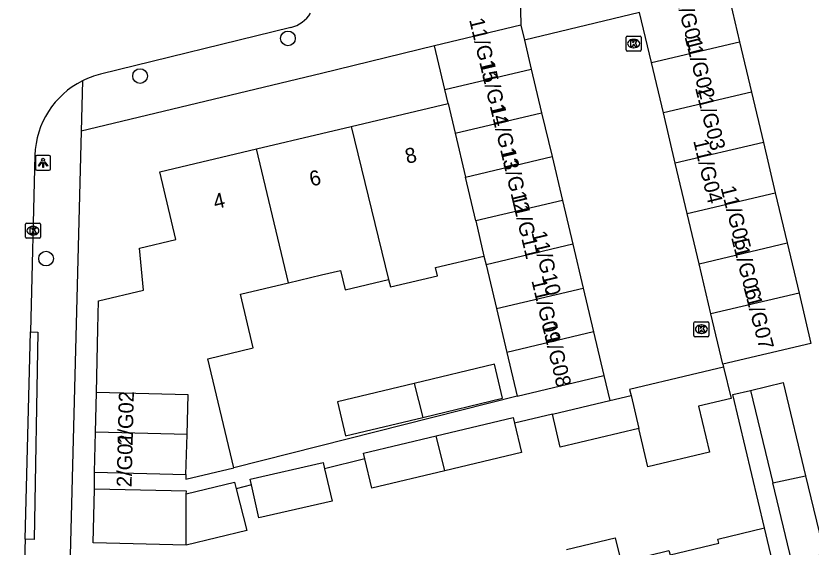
# Model space of a CAD drawing. Extents: x 162082 to 163393, y 388091 to 388632.
# Drawn here: x 162979.6 to 163032.6, y 388126.3 to 388161.7 of the extents above; entities that cross this region are included whole.
import ezdxf

# ---------------------------------------------------------------- set-up
doc = ezdxf.new("R2010")
doc.units = 0
for name, color, linetype in [('IMGEO_Boom', 7, 'Continuous'), ('IMGEO_Kolk', 7, 'Continuous'), ('IMGEO_Lichtpunt', 7, 'Continuous'), ('IMGEO_Muur', 7, 'Continuous'), ('IMGEO_Pand', 7, 'Continuous'), ('IMGEO_Pand_nummerreeks', 7, 'Continuous'), ('IMGEO_Rijbaan_lokaal_open', 7, 'Continuous'), ('IMGEO_Voetpad_open', 7, 'Continuous')]:
    doc.layers.add(name, color=color, linetype=linetype)

msp = doc.modelspace()

# ---------------------------------------------------------------- linework, layer by layer
at = {"layer": 'IMGEO_Boom'}
for centre in [(162997.773, 388160.238), (162987.922, 388157.727), (162981.659, 388145.557)]:
    msp.add_circle(centre, 0.489, dxfattribs=at)
at = {"layer": 'IMGEO_Kolk'}
for p, q in [((163020.299, 388159.464), (163020.299, 388160.316)), ((163020.374, 388160.39), (163021.226, 388160.39)), ((163020.787, 388160.17), (163020.812, 388160.17)), ((163021.3, 388160.316), (163021.3, 388159.464)), ((163020.81, 388159.61), (163020.785, 388159.61)), ((163021.226, 388159.39), (163020.374, 388159.39)), ((162980.285, 388146.994), (162980.285, 388147.846)), ((162980.36, 388147.92), (162981.212, 388147.92)), ((162981.286, 388147.846), (162981.286, 388146.994)), ((162980.773, 388147.7), (162980.798, 388147.7)), ((162981.212, 388146.92), (162980.36, 388146.92)), ((162980.796, 388147.14), (162980.771, 388147.14)), ((163024.813, 388140.43), (163024.813, 388141.282)), ((163024.888, 388141.356), (163025.74, 388141.356)), ((163025.301, 388141.136), (163025.326, 388141.136)), ((163025.814, 388141.282), (163025.814, 388140.43)), ((163025.74, 388140.356), (163024.888, 388140.356)), ((163025.324, 388140.576), (163025.299, 388140.576))]:
    msp.add_line(p, q, dxfattribs=at)
for points in [[(163020.299, 388159.464), (163020.299, 388160.316)], [(163020.374, 388160.39), (163021.226, 388160.39)], [(163020.62, 388160.09), (163020.743, 388160.09), (163020.743, 388159.939), (163020.873, 388160.09), (163021.037, 388160.09), (163020.891, 388159.939), (163021.044, 388159.69), (163020.892, 388159.69), (163020.807, 388159.854), (163020.743, 388159.787), (163020.743, 388159.69), (163020.62, 388159.69), (163020.62, 388160.09)], [(163021.3, 388160.316), (163021.3, 388159.464)], [(163021.226, 388159.39), (163020.374, 388159.39)], [(162980.285, 388146.994), (162980.285, 388147.846)], [(162980.36, 388147.92), (162981.212, 388147.92)], [(162981.286, 388147.846), (162981.286, 388146.994)], [(162980.606, 388147.62), (162980.729, 388147.62), (162980.729, 388147.469), (162980.859, 388147.62), (162981.023, 388147.62), (162980.877, 388147.469), (162981.03, 388147.22), (162980.878, 388147.22), (162980.793, 388147.384), (162980.729, 388147.317), (162980.729, 388147.22), (162980.606, 388147.22), (162980.606, 388147.62)], [(162981.212, 388146.92), (162980.36, 388146.92)], [(163024.813, 388140.43), (163024.813, 388141.282)], [(163024.888, 388141.356), (163025.74, 388141.356)], [(163025.134, 388141.056), (163025.257, 388141.056), (163025.257, 388140.905), (163025.387, 388141.056), (163025.551, 388141.056), (163025.405, 388140.905), (163025.558, 388140.656), (163025.406, 388140.656), (163025.321, 388140.82), (163025.257, 388140.753), (163025.257, 388140.656), (163025.134, 388140.656), (163025.134, 388141.056)], [(163025.814, 388141.282), (163025.814, 388140.43)], [(163025.74, 388140.356), (163024.888, 388140.356)]]:
    msp.add_lwpolyline(points, dxfattribs=at)
for centre, start, end in [((163020.376, 388160.314), 91.552, 178.448), ((163020.376, 388160.314), 91.552, 178.448), ((163021.224, 388160.314), 1.552, 88.448), ((163021.224, 388160.314), 1.552, 88.448), ((163020.376, 388159.466), 181.552, 268.448), ((163020.376, 388159.466), 181.552, 268.448), ((163021.224, 388159.466), 271.552, 358.448), ((163021.224, 388159.466), 271.552, 358.448), ((162980.362, 388147.844), 91.552, 178.448), ((162980.362, 388147.844), 91.552, 178.448), ((162981.21, 388147.844), 1.552, 88.448), ((162981.21, 388147.844), 1.552, 88.448), ((162980.362, 388146.996), 181.552, 268.448), ((162980.362, 388146.996), 181.552, 268.448), ((162981.21, 388146.996), 271.552, 358.448), ((162981.21, 388146.996), 271.552, 358.448), ((163024.89, 388141.28), 91.552, 178.448), ((163024.89, 388141.28), 91.552, 178.448), ((163025.738, 388141.28), 1.552, 88.448), ((163025.738, 388141.28), 1.552, 88.448), ((163024.89, 388140.432), 181.552, 268.448), ((163024.89, 388140.432), 181.552, 268.448), ((163025.738, 388140.432), 271.552, 358.448), ((163025.738, 388140.432), 271.552, 358.448)]:
    msp.add_arc(centre, 0.0765, start, end, dxfattribs=at)
for centre, major_axis, ratio, start_param, end_param in [((163020.786, 388159.89), (-0.387, 0.002), 0.722429, 4.712389, 7.853982), ((163020.811, 388159.89), (-0.39, 0.002), 0.717154, 1.570796, 4.712389), ((162980.772, 388147.42), (-0.387, 0.002), 0.722429, 4.712389, 7.853982), ((162980.797, 388147.42), (-0.39, 0.002), 0.717154, 1.570796, 4.712389), ((163025.3, 388140.856), (-0.387, 0.002), 0.722429, 4.712389, 7.853982), ((163025.325, 388140.856), (-0.39, 0.002), 0.717154, 1.570796, 4.712389)]:
    msp.add_ellipse(centre, major_axis=major_axis, ratio=ratio, start_param=start_param, end_param=end_param, dxfattribs=at)
at = {"layer": 'IMGEO_Lichtpunt'}
for p, q in [((162980.96, 388152.348), (162980.96, 388151.541)), ((162980.96, 388152.348), (162980.96, 388151.541)), ((162981.862, 388152.443), (162981.054, 388152.443)), ((162981.862, 388152.443), (162981.054, 388152.443)), ((162981.956, 388151.541), (162981.956, 388152.348)), ((162981.956, 388151.541), (162981.956, 388152.348)), ((162981.054, 388151.447), (162981.862, 388151.447)), ((162981.054, 388151.447), (162981.862, 388151.447))]:
    msp.add_line(p, q, dxfattribs=at)
for points in [[(162981.334, 388152.012), (162981.373, 388151.984), (162981.185, 388151.722), (162981.147, 388151.749), (162981.334, 388152.012)], [(162981.546, 388151.984), (162981.584, 388152.011), (162981.771, 388151.749), (162981.732, 388151.721), (162981.546, 388151.984)], [(162981.436, 388151.964), (162981.483, 388151.964), (162981.483, 388151.642), (162981.436, 388151.642), (162981.436, 388151.964)]]:
    msp.add_lwpolyline(points, dxfattribs=at)
msp.add_circle((162981.459, 388152.146), 0.0994, dxfattribs=at)
for centre, start, end in [((162981.054, 388152.348), 90, 180), ((162981.054, 388152.348), 90, 180), ((162981.862, 388152.348), 0, 90), ((162981.862, 388152.348), 0, 90), ((162981.054, 388151.541), 180, 270), ((162981.054, 388151.541), 180, 270), ((162981.862, 388151.541), 270, 0), ((162981.862, 388151.541), 270, 360)]:
    msp.add_arc(centre, 0.0946, start, end, dxfattribs=at)
at = {"layer": 'IMGEO_Muur'}
msp.add_lwpolyline([(162983.292, 388126.643), (162983.093, 388118.887)], dxfattribs=at)
at = {"layer": 'IMGEO_Pand'}
for points in [[(163027.064, 388163.356), (163027.856, 388160.006)], [(163021.992, 388158.62), (163021.2, 388161.969)], [(163013.29, 388161.115), (163007.525, 388159.751)], [(163013.29, 388161.115), (163013.524, 388160.125)], [(163013.524, 388160.125), (163013.981, 388158.196)], [(163021.992, 388158.62), (163027.856, 388160.006)], [(163027.856, 388160.006), (163028.648, 388156.656)], [(163008.216, 388156.831), (163007.525, 388159.751)], [(163022.784, 388155.269), (163021.992, 388158.62)], [(163008.216, 388156.831), (163013.981, 388158.196)], [(163013.981, 388158.196), (163014.672, 388155.277)], [(163008.439, 388155.888), (163008.216, 388156.831)], [(163028.648, 388156.656), (163022.784, 388155.269)], [(163028.648, 388156.656), (163029.44, 388153.306)], [(163001.99, 388154.362), (163008.439, 388155.888)], [(163008.439, 388155.888), (163008.904, 388153.911)], [(163008.904, 388153.911), (163014.672, 388155.277)], [(163014.672, 388155.277), (163015.363, 388152.358)], [(163023.576, 388151.919), (163022.784, 388155.269)], [(162995.687, 388152.87), (163000, 388153.891), (163001.99, 388154.362)], [(163001.99, 388154.362), (163004.479, 388144.174)], [(163008.904, 388153.911), (163009.59, 388150.991)], [(163029.44, 388153.306), (163023.576, 388151.919)], [(163029.44, 388153.306), (163030.232, 388149.955)], [(162985.012, 388136.641), (162985.117, 388140.885), (162985.163, 388142.746), (162988.151, 388143.454), (162987.876, 388146.263), (162990.309, 388146.839), (162989.242, 388151.344), (162995.687, 388152.87)], [(162997.798, 388143.951), (162995.687, 388152.87)], [(163009.59, 388150.991), (163015.363, 388152.358)], [(163015.363, 388152.358), (163016.054, 388149.439)], [(163024.368, 388148.569), (163023.576, 388151.919)], [(163010.277, 388148.071), (163009.59, 388150.991)], [(163024.368, 388148.569), (163030.232, 388149.955)], [(163030.232, 388149.955), (163031.024, 388146.605)], [(163016.054, 388149.439), (163010.277, 388148.071)], [(163016.054, 388149.439), (163016.745, 388146.519)], [(163025.16, 388145.219), (163024.368, 388148.569)], [(163010.277, 388148.071), (163010.827, 388145.732)], [(163016.745, 388146.519), (163010.965, 388145.151)], [(163016.745, 388146.519), (163017.436, 388143.6)], [(163025.16, 388145.219), (163031.024, 388146.605)], [(163031.024, 388146.605), (163031.816, 388143.255)], [(163004.479, 388144.174), (163004.596, 388143.68), (163007.733, 388144.423), (163007.604, 388144.969), (163010.827, 388145.732)], [(163010.827, 388145.732), (163010.965, 388145.151)], [(163010.965, 388145.151), (163011.656, 388142.232)], [(163025.952, 388141.869), (163025.16, 388145.219)], [(162997.798, 388143.951), (163000, 388144.472), (163001.277, 388144.774), (163001.581, 388143.489), (163004.479, 388144.174)], [(162994.164, 388131.611), (162992.441, 388138.891), (162995.456, 388139.605), (162994.606, 388143.195), (162997.798, 388143.951)], [(163011.656, 388142.232), (163017.436, 388143.6)], [(163017.436, 388143.6), (163018.127, 388140.681)], [(163031.816, 388143.255), (163025.952, 388141.869)], [(163031.816, 388143.255), (163032.608, 388139.905), (163026.744, 388138.518)], [(163011.656, 388142.232), (163012.347, 388139.313)], [(163026.744, 388138.518), (163025.952, 388141.869)], [(163018.127, 388140.681), (163012.347, 388139.313)], [(163018.127, 388140.681), (163018.818, 388137.762)], [(163012.347, 388139.313), (163013.038, 388136.394)], [(163006.747, 388134.974), (163012.07, 388136.254), (163011.522, 388138.53), (163006.19, 388137.246)], [(163026.79, 388138.328), (163024.622, 388137.815), (163020.53, 388136.847), (163020.627, 388136.435)], [(163026.79, 388138.328), (163027.287, 388136.232), (163025.118, 388135.719), (163025.843, 388132.657), (163021.75, 388131.689), (163021.147, 388134.239)], [(163013.038, 388136.394), (163018.818, 388137.762)], [(163006.19, 388137.246), (163001.069, 388136.014), (163001.616, 388133.739), (163006.747, 388134.974)], [(163006.19, 388137.246), (163006.747, 388134.974)], [(163028.593, 388136.779), (163030.759, 388137.3), (163032.254, 388131.088)], [(162984.946, 388133.989), (162985.012, 388136.641)], [(162991.053, 388133.835), (162991.132, 388136.478), (162985.012, 388136.641)], [(163028.593, 388136.779), (163030.078, 388130.611)], [(163015.392, 388135.197), (163019.223, 388136.103)], [(163019.223, 388136.103), (163020.627, 388136.435)], [(163020.627, 388136.435), (163021.147, 388134.239)], [(163021.147, 388134.239), (163015.911, 388133.001), (163015.392, 388135.197)], [(163007.649, 388133.745), (163012.763, 388134.969), (163012.854, 388134.588)], [(163012.854, 388134.588), (163013.32, 388132.643), (163008.227, 388131.425)], [(162984.88, 388131.337), (162984.946, 388133.989)], [(162991.053, 388133.835), (162984.946, 388133.989)], [(162990.972, 388131.168), (162991.053, 388133.835)], [(163002.888, 388132.215), (163002.8, 388132.584), (163007.649, 388133.745)], [(163008.227, 388131.425), (163007.649, 388133.745)], [(162995.34, 388130.478), (162995.254, 388130.853), (163000.121, 388131.964), (163000.215, 388131.551)], [(163008.227, 388131.425), (163003.357, 388130.259), (163002.888, 388132.215)], [(162984.88, 388131.337), (162990.972, 388131.168)], [(162990.972, 388131.168), (162990.963, 388130.853), (162994.164, 388131.611)], [(163000.215, 388131.551), (163000.709, 388129.388), (162995.842, 388128.278), (162995.34, 388130.478)], [(163030.078, 388130.611), (163032.254, 388131.088)], [(163032.254, 388131.088), (163033.511, 388125.868), (163031.565, 388125.399)], [(162991.001, 388129.89), (162994.209, 388130.666), (162994.322, 388130.219)], [(163031.565, 388125.399), (163031.346, 388125.346), (163030.078, 388130.611)], [(162991.001, 388126.47), (162984.799, 388126.609), (162984.88, 388130.204)], [(162991.001, 388129.89), (162991.005, 388130.066), (162984.88, 388130.204)], [(162994.322, 388130.219), (162995.024, 388127.441), (162991.001, 388126.47)], [(162991.001, 388126.47), (162991.001, 388129.89)], [(163022.972, 388126.058), (163023.153, 388126.101), (163023.223, 388125.809), (163026.465, 388126.588), (163026.399, 388126.861), (163029.513, 388127.607)], [(163031.936, 388117.503), (163030.77, 388122.366), (163029.513, 388127.607)], [(163016.329, 388126.175), (163019.576, 388126.954), (163019.964, 388125.336), (163022.972, 388126.058)]]:
    msp.add_lwpolyline(points, dxfattribs=at)
at = {"layer": 'IMGEO_Rijbaan_lokaal_open'}
for points in [[(163013.196, 388165.179), (163013.29, 388161.115)], [(163021.2, 388161.969), (163013.524, 388160.125)], [(162997.969, 388160.96), (162985.285, 388157.849)], [(162980.912, 388152.448), (162980.612, 388140.675)], [(162980.259, 388126.871), (162980.612, 388140.675)], [(163026.744, 388138.518), (163026.79, 388138.328)], [(163018.818, 388137.762), (163019.223, 388136.103)], [(162980.259, 388126.871), (162980.188, 388124.07), (162980.079, 388114.681), (162979.65, 388101.666)]]:
    msp.add_lwpolyline(points, dxfattribs=at)
for centre, radius, start, end in [((162997.461, 388163.029), 2.13, 283.7891, 328.7261), ((162986.673, 388152.218), 5.8, 103.8504, 116.5508), ((162986.652, 388152.271), 5.742, 116.593, 178.2361)]:
    msp.add_arc(centre, radius, start, end, dxfattribs=at)
at = {"layer": 'IMGEO_Voetpad_open'}
for points in [[(163007.525, 388159.751), (163000, 388157.905), (162983.995, 388154.044)], [(162984.081, 388157.406), (162983.995, 388154.044)], [(162983.995, 388154.044), (162983.292, 388126.643), (162983.093, 388118.887), (162982.649, 388101.605)], [(162980.612, 388140.675), (162981.111, 388140.658), (162980.865, 388126.85), (162980.259, 388126.871)], [(163029.513, 388127.607), (163027.41, 388136.499), (163028.593, 388136.779)], [(163013.038, 388136.394), (162994.164, 388131.611)], [(163015.392, 388135.197), (163012.854, 388134.588)], [(163002.888, 388132.215), (163000.215, 388131.551)], [(162984.88, 388130.204), (162984.88, 388131.337)], [(162995.34, 388130.478), (162994.322, 388130.219)]]:
    msp.add_lwpolyline(points, dxfattribs=at)

# ---------------------------------------------------------------- texts
at = {"layer": 'IMGEO_Pand_nummerreeks'}
for s, rotation, p in [('11/G01', 284.3952, (163023.421, 388163.606)), ('11/G15', 283.4185, (163009.836, 388161.481)), ('11/G02', 284.3952, (163024.182, 388160.346)), ('11/G14', 283.4194, (163010.531, 388158.568)), ('11/G03', 284.3952, (163024.883, 388156.937)), ('11/G13', 283.4194, (163011.226, 388155.656)), ('11/G04', 283.3015, (163024.764, 388153.415)), ('8', 13.3135, (163005.705, 388151.871)), ('11/G12', 283.4194, (163011.919, 388152.749)), ('6', 13.317, (162999.328, 388150.361)), ('4', 13.3155, (162992.929, 388148.846)), ('11/G05', 284.3952, (163026.584, 388150.284)), ('11/G11', 283.4194, (163012.641, 388149.723)), ('11/G10', 283.3182, (163013.995, 388147.285)), ('11/G06', 284.3952, (163027.283, 388146.972)), ('11/G09', 283.4194, (163013.984, 388144.096)), ('11/G07', 284.3952, (163028.107, 388143.669)), ('11/G08', 283.4194, (163014.68, 388141.177)), ('2/G02', 88.5735, (162987.424, 388133.075)), ('2/G01', 88.5735, (162987.356, 388130.319))]:
    msp.add_text(s, height=1, rotation=rotation, dxfattribs=at).set_placement(p)

doc.saveas('drawing.dxf')
